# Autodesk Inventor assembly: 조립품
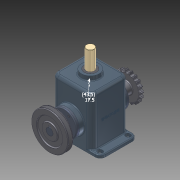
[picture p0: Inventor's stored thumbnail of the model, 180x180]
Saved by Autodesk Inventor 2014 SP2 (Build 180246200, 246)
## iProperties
Created: 2015-03
Part Number: 조립품
Document SubType Name: Assembly
Designer: 201-01
Mass: 8578.94 g
Surface Area: 4386.46 cm^2
Volume: 1982.49 cm^3
Density: 4.32735 g/cm^3
Author: 201-01
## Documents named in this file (15)
- C:\Users\201-01\Desktop\350305V1002\조립품.iam
- C:\Users\201-01\Desktop\350305V1002\본체.ipt
- C:\Users\201-01\Desktop\350305V1002\편심축.ipt
- C:\Users\201-01\Desktop\350305V1002\V-벨트풀리.ipt
- C:\Users\201-01\Desktop\350305V1002\체인 스프로킷.ipt
- C:\Users\201-01\Desktop\350305V1002\커버.ipt
- C:\Users\201-01\Desktop\350305V1002\슬라이드.ipt
- C:\Users\201-01\Desktop\350305V1002\가변스프링.ipt
- C:\Users\201-01\Desktop\350305V1002\베어링 6205.ipt
- C:\Users\201-01\Desktop\350305V1002\오일실.ipt
- C:\Users\201-01\Desktop\350305V1002\부시.ipt
- C:\Users\201-01\Desktop\350305V1002\키 8x8.ipt
- C:\Users\201-01\Desktop\350305V1002\멈춤링.ipt
- C:\Users\201-01\Desktop\350305V1002\M4x0.5.ipt
- C:\Users\201-01\Desktop\350305V1002\멈춤나사 M5x0.5.ipt
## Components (9 placed, 4 different names)
1. V-벨트풀리:1 — 각도:1, 플러쉬:1, 구동부
2. 5-체인 스프로킷:1 — 각도:2, 플러쉬:2
3. 가변스프링:1
4. M4x0.5:1 — 각도:5
5. M4x0.5:2
6. M4x0.5:3
7. M4x0.5:4 — 각도:6
8. M4x0.5:5
9. M4x0.5:6
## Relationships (7: Angle 5, Flush 2)
- 각도:1 [Angle]: V-벨트풀리:1
- 플러쉬:1 [Flush]: V-벨트풀리:1
- 각도:2 [Angle]: 5-체인 스프로킷:1
- 플러쉬:2 [Flush]: 5-체인 스프로킷:1
- 각도:5 [Angle]: M4x0.5:1
- 각도:6 [Angle]: M4x0.5:4
- 구동부 [Angle]: V-벨트풀리:1
